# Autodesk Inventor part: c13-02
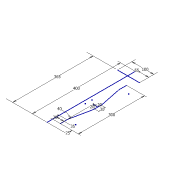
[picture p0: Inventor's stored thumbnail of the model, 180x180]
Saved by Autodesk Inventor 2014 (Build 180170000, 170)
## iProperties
Created: 2011-01
Part Number: c13-02
Material: Generic
Document SubType Name: Modeling
Designer: Thom Tremblay
Density: 1 g/cm^3
Appearance: Generic
Author: Thom Tremblay
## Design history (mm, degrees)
sketch "Sketch1"
  geometry: L1 (0, 0)-(0, 400); L2 (-45, 365)-(55, 365); L3 (35, 25)-(35, 55); L4 (35.827, 63.092)-(54.173, 151.908); L5 (55, 160)-(55, 190); L6 (54.173, 198.092)-(35.827, 286.908); L7 (35, 295)-(35, 325); L8 (55, 175)-(35, 175); A1 r 40 centre (75, 55) between (35.827, 63.092) and (35, 55); A2 r 40 centre (15, 160) between (54.173, 151.908) and (55, 160); A3 r 40 centre (15, 190) between (55, 190) and (54.173, 198.092); A4 r 40 centre (75, 295) between (35, 295) and (35.827, 286.908)
  constraints: 16 end point, 8 point on circle, 8 tangent, 4 centre point, 3 equal radius, 3 perpendicular, 2 equal length, 1 collinear, 1 midpoint, 1 parallel, 1 vertical
  dimensions: "d0" = 400 distance of L1.start L1.end; "d2" = 365 distance from line of L2 L1.start; "d3" = 100 distance of L2.start L2.end; "d4" = 55 horizontal distance of L2.end L1.end; "d5" = 30 distance of L3.start L3.end; "d6" = 40 radius of A1; "d7" = 35 distance between parallel lines of L1 L3; "d8" = 25 vertical distance of L3.start L1.start; "d9" = 20 distance between parallel lines of L5 L3; "d10" = 30 distance of L5.start L5.end; "d11" = 300 distance of L7.end L3.start; "d12" = 20 distance of L8.start L8.end (= d9)
